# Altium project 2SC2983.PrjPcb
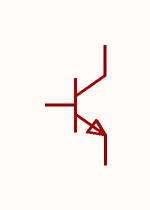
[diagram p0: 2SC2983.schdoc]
1 sheet, 1 parts. Net scope: global (net labels, ports and power ports of the same name join across sheets).

## Sheet 2SC2983.schdoc
size 127 x 101 mm

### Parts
Q?  2sc2983(range:120-240)  [TO-252-2_L6.5-W6.1-P4.58-LS10.0-TL]  (value not drawn)

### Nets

Not connected (* = marked no-connect by the designer): Q? 1(B) 3(E) 4(C)

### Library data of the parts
Q? = 2sc2983(range:120-240): 晶体管类型:NPN;集电极电流(Ic):1.5A;集射极击穿电压(Vceo):160V;耗散功率(Pd):1W;直流电流增益(hFE):120;; Manufacturer: CJ(江苏长电/长晶); AddInBom: yes; ModelId: 6b2ea0154a284e6db98f69bccdba3606; ModelName: TO-252-2_L6.5-W6.1-H2.3-LS10.0-P4.58; ModelTransform: 255.905,390.52442,0,270,0,0,38.183,0.432,0; type: NPN; Current - Collector(Ic): 1.5A; Collector - Emitter Voltage VCEO: 160V; Pd - Power Dissipation: 1W; DC Current Gain: 120; Transition frequency(fT): 100MHz; Current - Collector Cutoff: 1uA; Vce Saturation(VCE(sat)): 1.5V; Emitter-Base Voltage(Vebo): 5V; Number: 1个NPN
